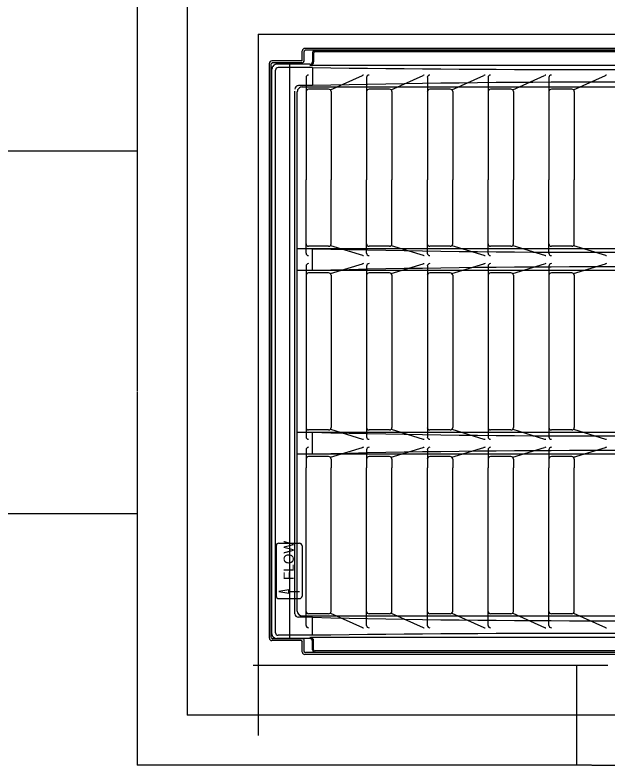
# Model space of a CAD drawing. Extents: x 2.4 to 9.7, y 1.1 to 11.2.
# Drawn here: x 5.797 to 6.811, y 5.195 to 6.478 of the extents above; entities that cross this region are included whole.
import ezdxf

# ---------------------------------------------------------------- set-up
doc = ezdxf.new("R2010")
doc.units = 0
doc.layers.add('DETL-LINE', color=7, linetype='Continuous')
doc.layers.add('DETL-NOTE', color=7, linetype='Continuous')

msp = doc.modelspace()

# ---------------------------------------------------------------- linework, layer by layer
at = {"layer": 'DETL-LINE'}
for p, q in [((6.0058, 7.0975), (6.0058, 5.8344)), ((6.091, 6.5054), (6.091, 5.2799)), ((6.2124, 6.4451), (6.2124, 5.245)), ((6.2124, 6.4451), (6.8306, 6.4451)), ((6.288, 6.4013), (6.288, 6.4166)), ((7.3229, 6.4207), (6.2924, 6.4207)), ((7.3218, 6.4176), (6.2935, 6.4176)), ((6.2913, 6.4003), (6.2913, 6.4155)), ((6.3074, 6.4125), (6.3074, 6.3977)), ((7.3055, 6.4146), (6.3097, 6.4146)), ((6.2317, 5.4117), (6.2317, 6.3952)), ((6.235, 5.4127), (6.235, 6.3941)), ((6.2859, 6.3993), (6.2361, 6.3993)), ((6.287, 6.3962), (6.2372, 6.3962)), ((6.2664, 6.3936), (6.2664, 6.3962)), ((6.2664, 5.4109), (6.2664, 6.3936)), ((7.3142, 6.3917), (6.3018, 6.3917)), ((6.2422, 5.4208), (6.2422, 6.3837)), ((6.3054, 6.3878), (6.2466, 6.3878)), ((6.3054, 6.3878), (6.3054, 6.357)), ((6.3054, 6.357), (6.2817, 6.357)), ((6.288, 6.3547), (7.3272, 6.3547)), ((6.2752, 5.4536), (6.2752, 6.3475)), ((6.2794, 5.458), (6.2794, 6.3465)), ((6.0058, 6.2449), (5.6575, 6.2449)), ((7.3359, 6.078), (6.2794, 6.078)), ((6.3054, 6.0407), (6.3054, 6.078)), ((7.3359, 6.0407), (6.2794, 6.0407)), ((6.0058, 5.8332), (6.0058, 5.1947)), ((7.3359, 5.7638), (6.2794, 5.7638)), ((6.3054, 5.7265), (6.3054, 5.7638)), ((7.3359, 5.7265), (6.2794, 5.7265)), ((6.0058, 5.6245), (5.6575, 5.6245)), ((6.3054, 5.4475), (6.2817, 5.4475)), ((6.288, 5.4498), (7.3272, 5.4498)), ((6.3054, 5.4167), (6.3054, 5.4475)), ((6.3054, 5.4167), (6.2466, 5.4167)), ((6.2859, 5.4076), (6.2361, 5.4076)), ((6.2891, 5.4107), (6.2372, 5.4107)), ((6.2664, 5.4107), (6.2664, 5.4109)), ((6.288, 5.3879), (6.288, 5.4055)), ((6.2913, 5.389), (6.2913, 5.4086)), ((7.3142, 5.4128), (6.3018, 5.4128)), ((6.3074, 5.392), (6.3074, 5.4068)), ((7.3055, 5.3899), (6.3097, 5.3899)), ((7.3229, 5.3838), (6.2924, 5.3838)), ((7.3218, 5.3869), (6.2935, 5.3869)), ((6.8102, 5.3652), (6.2041, 5.3652)), ((6.7574, 5.1947), (6.7574, 5.3652)), ((8.6877, 5.2799), (6.091, 5.2799)), ((6.7823, 5.1947), (6.0058, 5.1947)), ((6.7833, 5.1947), (7.2189, 5.1947))]:
    msp.add_line(p, q, dxfattribs=at)
for centre, major_axis, start_param, end_param in [((6.2924, 6.4166), (0.00433, 0), 1.570796, 3.141593), ((6.2935, 6.4155), (0.00216, 0), 1.570796, 3.141593), ((6.3097, 6.4125), (0.00229, 0), 1.570796, 3.141593), ((6.2361, 6.3952), (0.00433, 0), 1.570796, 3.141593), ((6.2372, 6.3941), (0.00216, 0), 1.570796, 3.141593), ((6.2859, 6.4013), (0.00216, 0), 4.712389, 6.283185), ((6.287, 6.4003), (0.00433, 0), 4.712389, 6.283185), ((6.301, 6.3977), (0.00637, 0), 4.712389, 6.283185), ((6.2466, 6.3837), (0.00433, 0), 1.570796, 3.141593), ((6.8076, 40.9898), (36.4153, 0), 4.698596, 4.726182), ((6.8076, -12.9443), (20.3171, 0), 1.546073, 1.59552), ((6.2817, 6.3508), (0.00649, 0), 1.570796, 3.141593), ((6.288, 6.3465), (0.00866, 0), 1.570796, 3.141593), ((6.8076, 24.5302), (19.4238, 0), 4.686528, 4.73825), ((6.8076, -12.4115), (19.4238, 0), 1.544936, 1.596657), ((6.8076, 24.216), (19.4238, 0), 4.686528, 4.73825), ((6.8076, -12.7257), (19.4238, 0), 1.544936, 1.596657), ((6.2817, 5.4536), (0.00649, 0), 3.141593, 4.712389), ((6.288, 5.458), (0.00866, 0), 3.141593, 4.712389), ((6.8076, 24.7487), (20.3171, 0), 4.687666, 4.737112), ((6.2466, 5.4208), (0.00433, 0), 3.141593, 4.712389), ((6.8076, -29.1853), (36.4153, 0), 1.557003, 1.584589), ((6.2361, 5.4117), (0.00433, 0), 3.141593, 4.712389), ((6.2372, 5.4127), (0.00216, 0), 3.141593, 4.712389), ((6.2859, 5.4055), (0.00216, 0), 0, 1.570796), ((6.2891, 5.4086), (0.00216, 0), 0, 1.570796), ((6.301, 5.4068), (0.00637, 0), 0, 1.570796), ((6.3097, 5.392), (0.00229, 0), 3.141593, 4.712389), ((6.2924, 5.3879), (0.00433, 0), 3.141593, 4.712389), ((6.2935, 5.389), (0.00216, 0), 3.141593, 4.712389)]:
    msp.add_ellipse(centre, major_axis=major_axis, ratio=0.950294, start_param=start_param, end_param=end_param, dxfattribs=at)
at = {"layer": 'DETL-NOTE'}
for p, q in [((6.3097, 6.4166), (7.3055, 6.4166)), ((6.3054, 6.4125), (6.3054, 6.3977)), ((6.301, 6.3936), (6.2447, 6.3936)), ((6.3054, 6.4018), (6.3054, 6.3978)), ((6.2361, 5.4191), (6.2361, 6.3854)), ((6.2945, 6.3709), (6.2945, 6.1961)), ((6.3361, 6.3498), (6.3907, 6.3746)), ((6.3979, 6.3709), (6.3979, 6.1961)), ((6.44, 6.3498), (6.4946, 6.3746)), ((6.5018, 6.3709), (6.5018, 6.1961)), ((6.5439, 6.3498), (6.5985, 6.3746)), ((6.6057, 6.3709), (6.6057, 6.1961)), ((6.6478, 6.3498), (6.7024, 6.3746)), ((6.7096, 6.3709), (6.7096, 6.1961)), ((6.7517, 6.3498), (6.8063, 6.3746)), ((6.333, 6.351), (6.2988, 6.351)), ((6.3373, 6.3468), (6.3373, 6.1961)), ((6.4369, 6.351), (6.4022, 6.351)), ((6.4413, 6.3468), (6.4413, 6.1961)), ((6.5408, 6.351), (6.5061, 6.351)), ((6.5452, 6.3468), (6.5452, 6.1961)), ((6.6448, 6.351), (6.61, 6.351)), ((6.6491, 6.3468), (6.6491, 6.1961)), ((6.7487, 6.351), (6.714, 6.351)), ((6.753, 6.3468), (6.753, 6.1961)), ((6.2945, 6.0704), (6.2945, 6.1961)), ((6.3373, 6.0863), (6.3373, 6.1961)), ((6.3979, 6.0704), (6.3979, 6.1961)), ((6.4413, 6.0863), (6.4413, 6.1961)), ((6.5018, 6.0704), (6.5018, 6.1961)), ((6.5452, 6.0863), (6.5452, 6.1961)), ((6.6057, 6.0704), (6.6057, 6.1961)), ((6.6491, 6.0863), (6.6491, 6.1961)), ((6.7096, 6.0704), (6.7096, 6.1961)), ((6.753, 6.0863), (6.753, 6.1961)), ((6.333, 6.0821), (6.2988, 6.0821)), ((6.3361, 6.0834), (6.3907, 6.0667)), ((6.4369, 6.0821), (6.4022, 6.0821)), ((6.44, 6.0834), (6.4946, 6.0667)), ((6.5408, 6.0821), (6.5061, 6.0821)), ((6.5439, 6.0834), (6.5985, 6.0667)), ((6.6448, 6.0821), (6.61, 6.0821)), ((6.6478, 6.0834), (6.7024, 6.0667)), ((6.7487, 6.0821), (6.714, 6.0821)), ((6.7517, 6.0834), (6.8063, 6.0667)), ((6.2945, 6.0483), (6.2945, 5.7561)), ((6.3361, 6.0354), (6.3907, 6.0521)), ((6.3979, 6.0483), (6.3979, 5.7561)), ((6.44, 6.0354), (6.4946, 6.0521)), ((6.5018, 6.0483), (6.5018, 5.7561)), ((6.5439, 6.0354), (6.5985, 6.0521)), ((6.6057, 6.0483), (6.6057, 5.7561)), ((6.6478, 6.0354), (6.7024, 6.0521)), ((6.7096, 6.0483), (6.7096, 5.7561)), ((6.7517, 6.0354), (6.8063, 6.0521)), ((6.333, 6.0366), (6.2988, 6.0366)), ((6.3373, 6.0325), (6.3373, 5.772)), ((6.4369, 6.0366), (6.4022, 6.0366)), ((6.4413, 6.0325), (6.4413, 5.772)), ((6.5408, 6.0366), (6.5061, 6.0366)), ((6.5452, 6.0325), (6.5452, 5.772)), ((6.6448, 6.0366), (6.61, 6.0366)), ((6.6491, 6.0325), (6.6491, 5.772)), ((6.7487, 6.0366), (6.714, 6.0366)), ((6.753, 6.0325), (6.753, 5.772)), ((6.333, 5.7679), (6.2988, 5.7679)), ((6.3361, 5.7691), (6.3907, 5.7524)), ((6.4369, 5.7679), (6.4022, 5.7679)), ((6.44, 5.7691), (6.4946, 5.7524)), ((6.5408, 5.7679), (6.5061, 5.7679)), ((6.5439, 5.7691), (6.5985, 5.7524)), ((6.6448, 5.7679), (6.61, 5.7679)), ((6.6478, 5.7691), (6.7024, 5.7524)), ((6.7487, 5.7679), (6.714, 5.7679)), ((6.7517, 5.7691), (6.8063, 5.7524)), ((6.3361, 5.7211), (6.3907, 5.7378)), ((6.44, 5.7211), (6.4946, 5.7378)), ((6.5439, 5.7211), (6.5985, 5.7378)), ((6.6478, 5.7211), (6.7024, 5.7378)), ((6.7517, 5.7211), (6.8063, 5.7378)), ((6.2945, 5.7341), (6.2945, 5.703)), ((6.3979, 5.7341), (6.3979, 5.703)), ((6.5018, 5.7341), (6.5018, 5.703)), ((6.6057, 5.7341), (6.6057, 5.703)), ((6.7096, 5.7341), (6.7096, 5.703)), ((6.333, 5.7223), (6.2988, 5.7223)), ((6.3373, 5.7182), (6.3373, 5.703)), ((6.4369, 5.7223), (6.4022, 5.7223)), ((6.4413, 5.7182), (6.4413, 5.703)), ((6.5408, 5.7223), (6.5061, 5.7223)), ((6.5452, 5.7182), (6.5452, 5.703)), ((6.6448, 5.7223), (6.61, 5.7223)), ((6.6491, 5.7182), (6.6491, 5.703)), ((6.7487, 5.7223), (6.714, 5.7223)), ((6.753, 5.7182), (6.753, 5.703)), ((6.2945, 5.4336), (6.2945, 5.703)), ((6.3373, 5.4576), (6.3373, 5.703)), ((6.3979, 5.4336), (6.3979, 5.703)), ((6.4413, 5.4576), (6.4413, 5.703)), ((6.5018, 5.4336), (6.5018, 5.703)), ((6.5452, 5.4576), (6.5452, 5.703)), ((6.6057, 5.4336), (6.6057, 5.703)), ((6.6491, 5.4576), (6.6491, 5.703)), ((6.7096, 5.4336), (6.7096, 5.703)), ((6.753, 5.4576), (6.753, 5.703)), ((6.2434, 5.5699), (6.2434, 5.4834)), ((6.2477, 5.574), (6.2832, 5.574)), ((6.2875, 5.5699), (6.2875, 5.4834)), ((6.2477, 5.4793), (6.2832, 5.4793)), ((6.265, 5.4916), (6.283, 5.4916)), ((6.333, 5.4535), (6.2988, 5.4535)), ((6.3361, 5.4547), (6.3907, 5.4298)), ((6.4369, 5.4535), (6.4022, 5.4535)), ((6.44, 5.4547), (6.4946, 5.4298)), ((6.5408, 5.4535), (6.5061, 5.4535)), ((6.5439, 5.4547), (6.5985, 5.4298)), ((6.6448, 5.4535), (6.61, 5.4535)), ((6.6478, 5.4547), (6.7024, 5.4298)), ((6.7487, 5.4535), (6.714, 5.4535)), ((6.7517, 5.4547), (6.8063, 5.4298)), ((6.301, 5.4109), (6.2447, 5.4109)), ((6.3054, 5.392), (6.3054, 5.4068)), ((6.3054, 5.4027), (6.3054, 5.4067)), ((6.3097, 5.3879), (7.3055, 5.3879))]:
    msp.add_line(p, q, dxfattribs=at)
msp.add_lwpolyline([(6.265, 5.4889), (6.265, 5.4944), (6.2477, 5.4916)], close=True, dxfattribs=at)
for centre, major_axis, start_param, end_param in [((6.3097, 6.4125), (0.00433, 0), 1.570796, 3.141593), ((6.2447, 6.3854), (0.00866, 0), 1.570796, 3.141593), ((6.301, 6.3977), (0.00433, 0), 4.712389, 6.283185), ((6.2988, 6.3709), (0.00433, 0), 1.570796, 3.141593), ((6.3926, 6.3709), (0.00433, 0), 1.570796, 2.018093), ((6.4022, 6.3709), (0.00433, 0), 1.570796, 3.141593), ((6.4965, 6.3709), (0.00433, 0), 1.570796, 2.018093), ((6.5061, 6.3709), (0.00433, 0), 1.570796, 3.141593), ((6.6004, 6.3709), (0.00433, 0), 1.570796, 2.018093), ((6.61, 6.3709), (0.00433, 0), 1.570796, 3.141593), ((6.7043, 6.3709), (0.00433, 0), 1.570796, 2.018093), ((6.714, 6.3709), (0.00433, 0), 1.570796, 3.141593), ((6.8082, 6.3709), (0.00433, 0), 1.570796, 2.018093), ((6.2988, 6.3468), (0.00433, 0), 1.570796, 3.141593), ((6.333, 6.3468), (0.00433, 0), 0, 1.570796), ((6.4022, 6.3468), (0.00433, 0), 1.570796, 3.141593), ((6.4369, 6.3468), (0.00433, 0), 0, 1.570796), ((6.5061, 6.3468), (0.00433, 0), 1.570796, 3.141593), ((6.5408, 6.3468), (0.00433, 0), 0, 1.570796), ((6.61, 6.3468), (0.00433, 0), 1.570796, 3.141593), ((6.6448, 6.3468), (0.00433, 0), 0, 1.570796), ((6.714, 6.3468), (0.00433, 0), 1.570796, 3.141593), ((6.7487, 6.3468), (0.00433, 0), 0, 1.570796), ((6.2988, 6.0863), (0.00433, 0), 3.141593, 4.712389), ((6.333, 6.0863), (0.00433, 0), 4.712389, 6.283185), ((6.4022, 6.0863), (0.00433, 0), 3.141593, 4.712389), ((6.4369, 6.0863), (0.00433, 0), 4.712389, 6.283185), ((6.5061, 6.0863), (0.00433, 0), 3.141593, 4.712389), ((6.5408, 6.0863), (0.00433, 0), 4.712389, 6.283185), ((6.61, 6.0863), (0.00433, 0), 3.141593, 4.712389), ((6.6448, 6.0863), (0.00433, 0), 4.712389, 6.283185), ((6.714, 6.0863), (0.00433, 0), 3.141593, 4.712389), ((6.7487, 6.0863), (0.00433, 0), 4.712389, 6.283185), ((6.2988, 6.0704), (0.00433, 0), 3.141593, 4.712389), ((6.4022, 6.0704), (0.00433, 0), 3.141593, 4.712389), ((6.5061, 6.0704), (0.00433, 0), 3.141593, 4.712389), ((6.61, 6.0704), (0.00433, 0), 3.141593, 4.712389), ((6.714, 6.0704), (0.00433, 0), 3.141593, 4.712389), ((6.3926, 6.0704), (0.00433, 0), 4.265092, 4.712389), ((6.4965, 6.0704), (0.00433, 0), 4.265092, 4.712389), ((6.6004, 6.0704), (0.00433, 0), 4.265092, 4.712389), ((6.7043, 6.0704), (0.00433, 0), 4.265092, 4.712389), ((6.8082, 6.0704), (0.00433, 0), 4.265092, 4.712389), ((6.2988, 6.0483), (0.00433, 0), 1.570796, 3.141593), ((6.3926, 6.0483), (0.00433, 0), 1.570796, 2.018093), ((6.4022, 6.0483), (0.00433, 0), 1.570796, 3.141593), ((6.4965, 6.0483), (0.00433, 0), 1.570796, 2.018093), ((6.5061, 6.0483), (0.00433, 0), 1.570796, 3.141593), ((6.6004, 6.0483), (0.00433, 0), 1.570796, 2.018093), ((6.61, 6.0483), (0.00433, 0), 1.570796, 3.141593), ((6.7043, 6.0483), (0.00433, 0), 1.570796, 2.018093), ((6.714, 6.0483), (0.00433, 0), 1.570796, 3.141593), ((6.8082, 6.0483), (0.00433, 0), 1.570796, 2.018093), ((6.2988, 6.0325), (0.00433, 0), 1.570796, 3.141593), ((6.333, 6.0325), (0.00433, 0), 0, 1.570796), ((6.4022, 6.0325), (0.00433, 0), 1.570796, 3.141593), ((6.4369, 6.0325), (0.00433, 0), 0, 1.570796), ((6.5061, 6.0325), (0.00433, 0), 1.570796, 3.141593), ((6.5408, 6.0325), (0.00433, 0), 0, 1.570796), ((6.61, 6.0325), (0.00433, 0), 1.570796, 3.141593), ((6.6448, 6.0325), (0.00433, 0), 0, 1.570796), ((6.714, 6.0325), (0.00433, 0), 1.570796, 3.141593), ((6.7487, 6.0325), (0.00433, 0), 0, 1.570796), ((6.2988, 5.772), (0.00433, 0), 3.141593, 4.712389), ((6.333, 5.772), (0.00433, 0), 4.712389, 6.283185), ((6.4022, 5.772), (0.00433, 0), 3.141593, 4.712389), ((6.4369, 5.772), (0.00433, 0), 4.712389, 6.283185), ((6.5061, 5.772), (0.00433, 0), 3.141593, 4.712389), ((6.5408, 5.772), (0.00433, 0), 4.712389, 6.283185), ((6.61, 5.772), (0.00433, 0), 3.141593, 4.712389), ((6.6448, 5.772), (0.00433, 0), 4.712389, 6.283185), ((6.714, 5.772), (0.00433, 0), 3.141593, 4.712389), ((6.7487, 5.772), (0.00433, 0), 4.712389, 6.283185), ((6.2988, 5.7561), (0.00433, 0), 3.141593, 4.712389), ((6.3926, 5.7561), (0.00433, 0), 4.265092, 4.712389), ((6.4022, 5.7561), (0.00433, 0), 3.141593, 4.712389), ((6.4965, 5.7561), (0.00433, 0), 4.265092, 4.712389), ((6.5061, 5.7561), (0.00433, 0), 3.141593, 4.712389), ((6.6004, 5.7561), (0.00433, 0), 4.265092, 4.712389), ((6.61, 5.7561), (0.00433, 0), 3.141593, 4.712389), ((6.7043, 5.7561), (0.00433, 0), 4.265092, 4.712389), ((6.714, 5.7561), (0.00433, 0), 3.141593, 4.712389), ((6.8082, 5.7561), (0.00433, 0), 4.265092, 4.712389), ((6.2988, 5.7341), (0.00433, 0), 1.570796, 3.141593), ((6.3926, 5.7341), (0.00433, 0), 1.570796, 2.018093), ((6.4022, 5.7341), (0.00433, 0), 1.570796, 3.141593), ((6.4965, 5.7341), (0.00433, 0), 1.570796, 2.018093), ((6.5061, 5.7341), (0.00433, 0), 1.570796, 3.141593), ((6.6004, 5.7341), (0.00433, 0), 1.570796, 2.018093), ((6.61, 5.7341), (0.00433, 0), 1.570796, 3.141593), ((6.7043, 5.7341), (0.00433, 0), 1.570796, 2.018093), ((6.714, 5.7341), (0.00433, 0), 1.570796, 3.141593), ((6.8082, 5.7341), (0.00433, 0), 1.570796, 2.018093), ((6.2988, 5.7182), (0.00433, 0), 1.570796, 3.141593), ((6.333, 5.7182), (0.00433, 0), 0, 1.570796), ((6.4022, 5.7182), (0.00433, 0), 1.570796, 3.141593), ((6.4369, 5.7182), (0.00433, 0), 0, 1.570796), ((6.5061, 5.7182), (0.00433, 0), 1.570796, 3.141593), ((6.5408, 5.7182), (0.00433, 0), 0, 1.570796), ((6.61, 5.7182), (0.00433, 0), 1.570796, 3.141593), ((6.6448, 5.7182), (0.00433, 0), 0, 1.570796), ((6.714, 5.7182), (0.00433, 0), 1.570796, 3.141593), ((6.7487, 5.7182), (0.00433, 0), 0, 1.570796), ((6.2477, 5.5699), (0.00433, 0), 1.570796, 3.141593), ((6.2832, 5.5699), (0.00433, 0), 0, 1.570796), ((6.2477, 5.4834), (0.00433, 0), 3.141593, 4.712389), ((6.2832, 5.4834), (0.00433, 0), 4.712389, 6.283185), ((6.2988, 5.4576), (0.00433, 0), 3.141593, 4.712389), ((6.333, 5.4576), (0.00433, 0), 4.712389, 6.283185), ((6.4022, 5.4576), (0.00433, 0), 3.141593, 4.712389), ((6.4369, 5.4576), (0.00433, 0), 4.712389, 6.283185), ((6.5061, 5.4576), (0.00433, 0), 3.141593, 4.712389), ((6.5408, 5.4576), (0.00433, 0), 4.712389, 6.283185), ((6.61, 5.4576), (0.00433, 0), 3.141593, 4.712389), ((6.6448, 5.4576), (0.00433, 0), 4.712389, 6.283185), ((6.714, 5.4576), (0.00433, 0), 3.141593, 4.712389), ((6.7487, 5.4576), (0.00433, 0), 4.712389, 6.283185), ((6.2988, 5.4336), (0.00433, 0), 3.141593, 4.712389), ((6.3926, 5.4336), (0.00433, 0), 4.265092, 4.712389), ((6.4022, 5.4336), (0.00433, 0), 3.141593, 4.712389), ((6.4965, 5.4336), (0.00433, 0), 4.265092, 4.712389), ((6.5061, 5.4336), (0.00433, 0), 3.141593, 4.712389), ((6.6004, 5.4336), (0.00433, 0), 4.265092, 4.712389), ((6.61, 5.4336), (0.00433, 0), 3.141593, 4.712389), ((6.7043, 5.4336), (0.00433, 0), 4.265092, 4.712389), ((6.714, 5.4336), (0.00433, 0), 3.141593, 4.712389), ((6.8082, 5.4336), (0.00433, 0), 4.265092, 4.712389), ((6.2447, 5.4191), (0.00866, 0), 3.141593, 4.712389), ((6.301, 5.4068), (0.00433, 0), 0, 1.570796), ((6.3097, 5.392), (0.00433, 0), 3.141593, 4.712389)]:
    msp.add_ellipse(centre, major_axis=major_axis, ratio=0.950294, start_param=start_param, end_param=end_param, dxfattribs=at)

# ---------------------------------------------------------------- texts
msp.add_text('FLOW', height=0.01732, rotation=90, dxfattribs=at).set_placement((6.2734, 5.5113))

doc.saveas('drawing.dxf')
